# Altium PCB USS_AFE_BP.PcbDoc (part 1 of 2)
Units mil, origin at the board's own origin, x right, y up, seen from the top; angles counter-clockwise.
Board outline 2300 x 2500 mil, 4 copper layers (Top Layer, GND, PWR, Bottom Layer), stack 59 mil thick; 119 components, 70 nets, 303 pads, 68 vias.
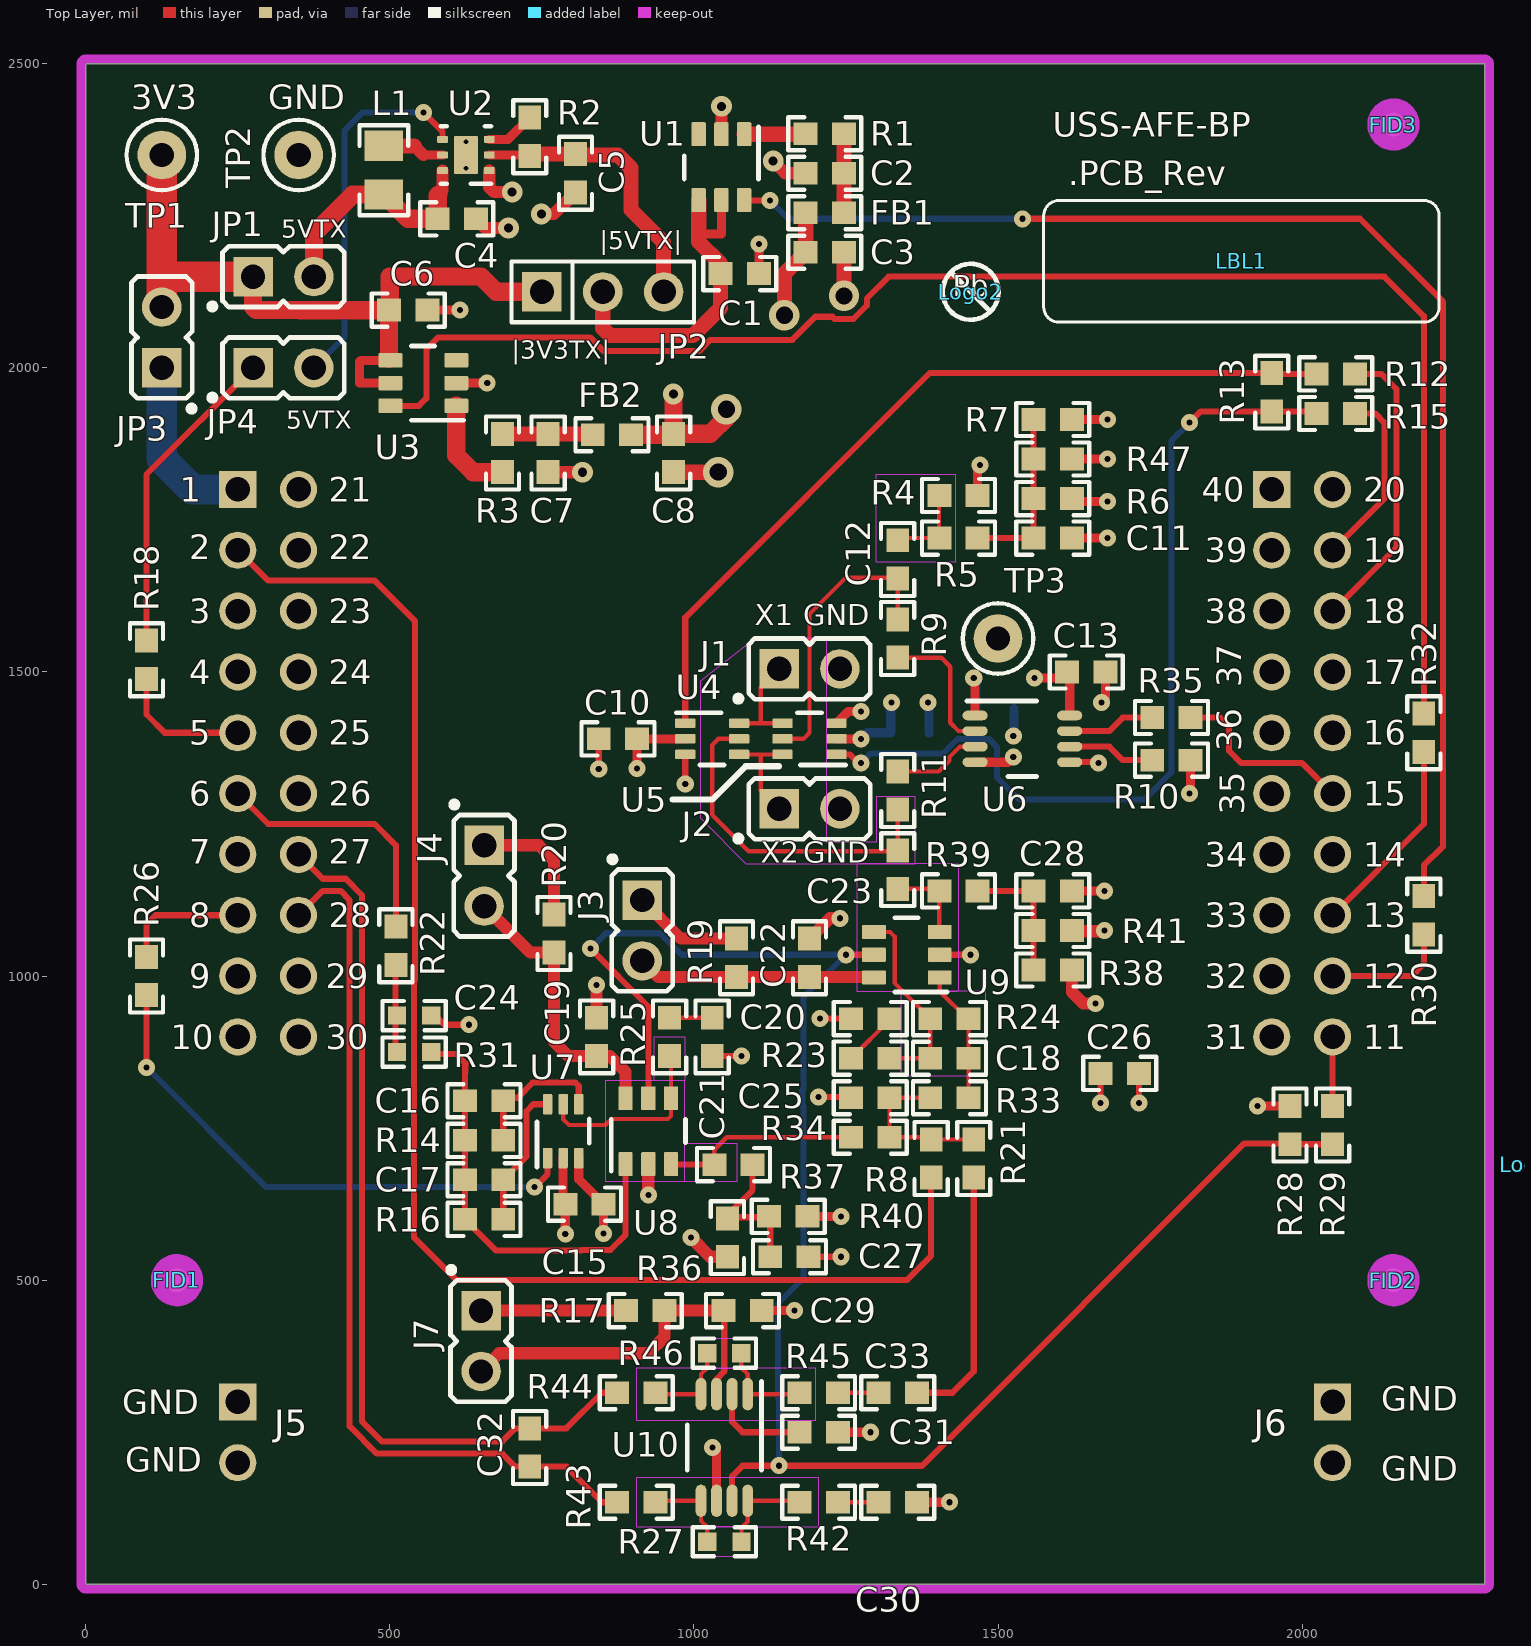
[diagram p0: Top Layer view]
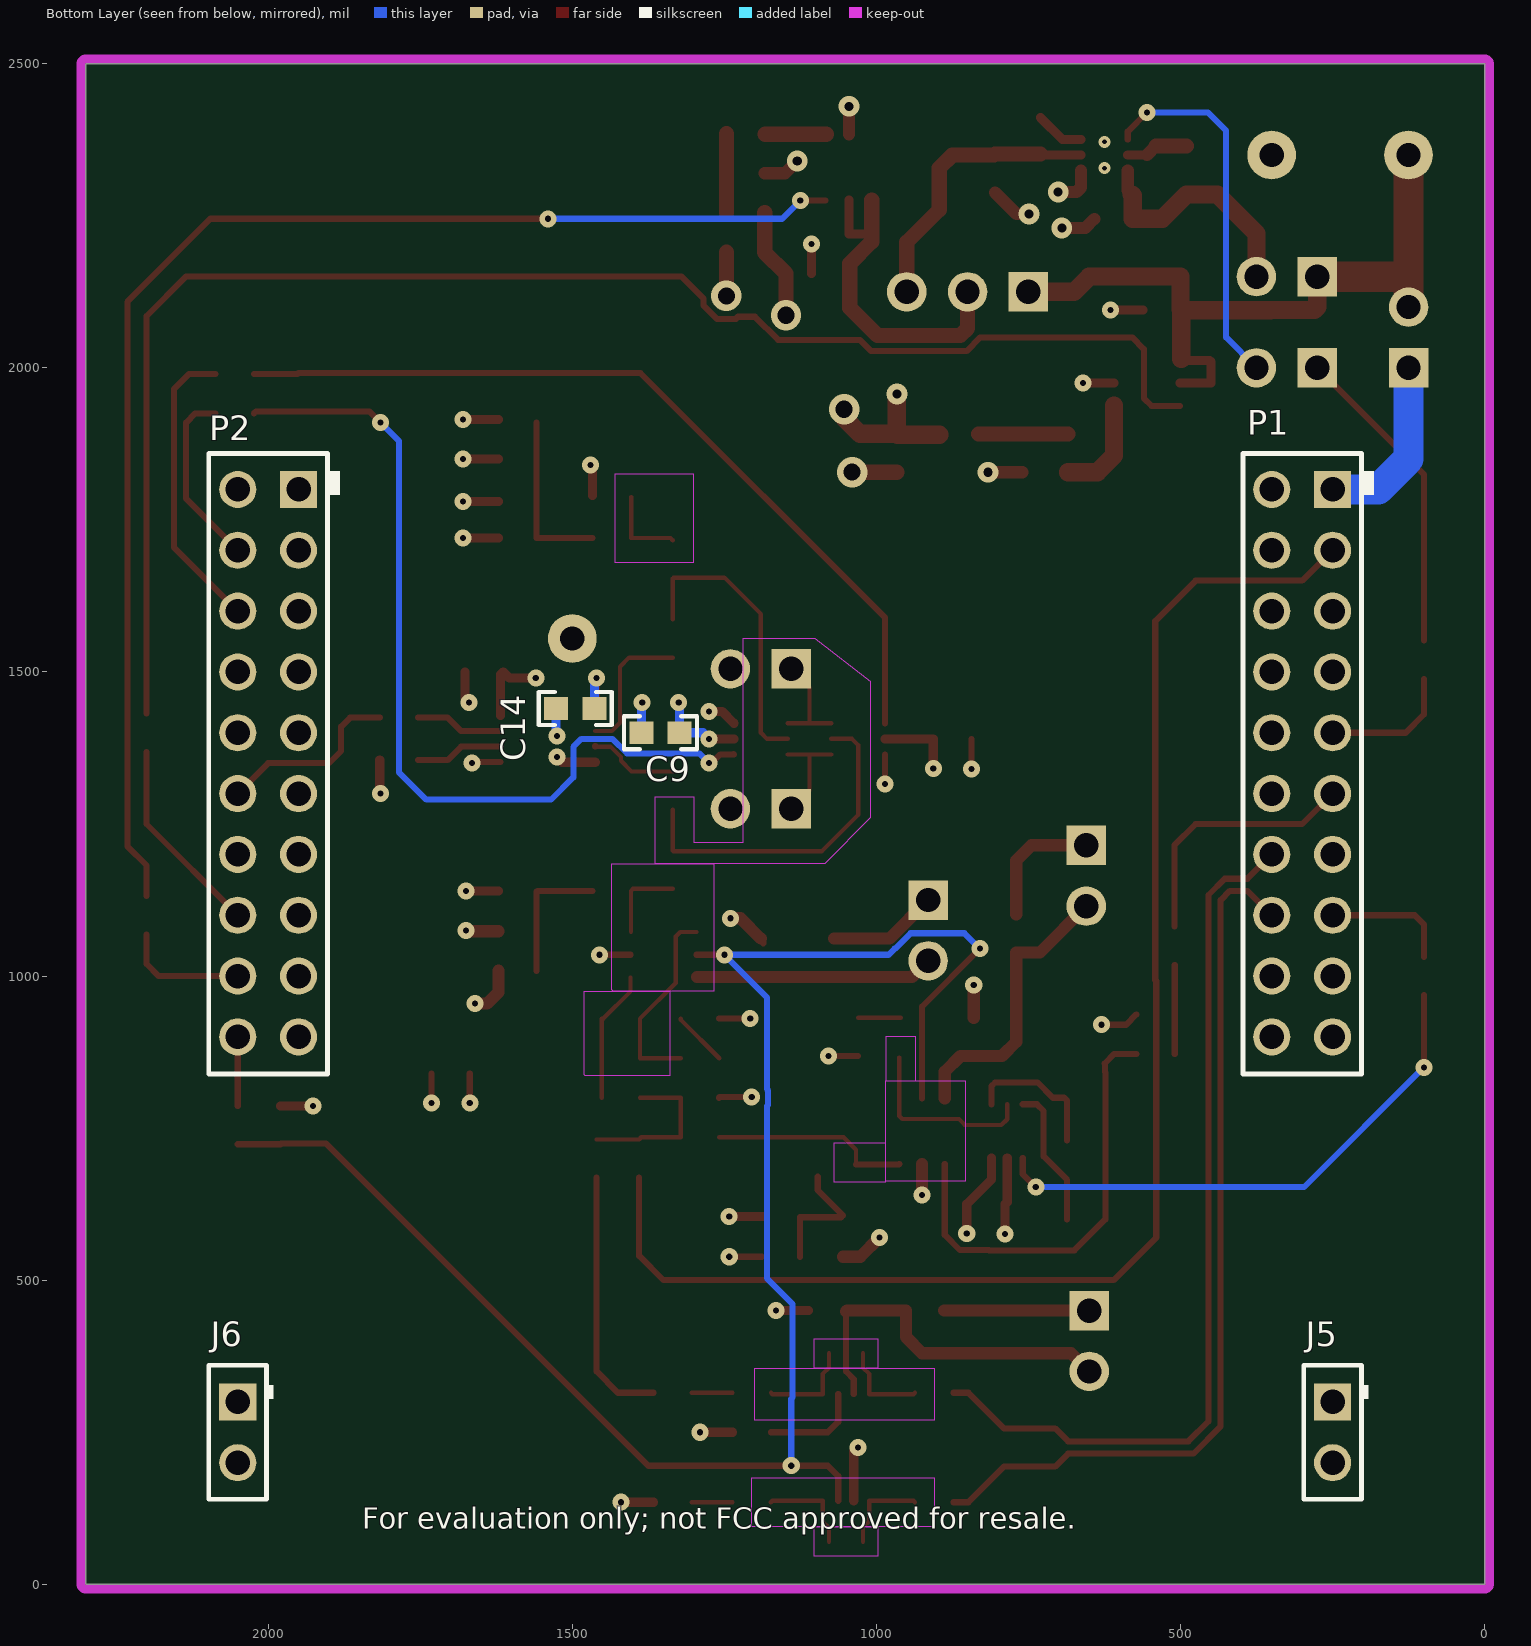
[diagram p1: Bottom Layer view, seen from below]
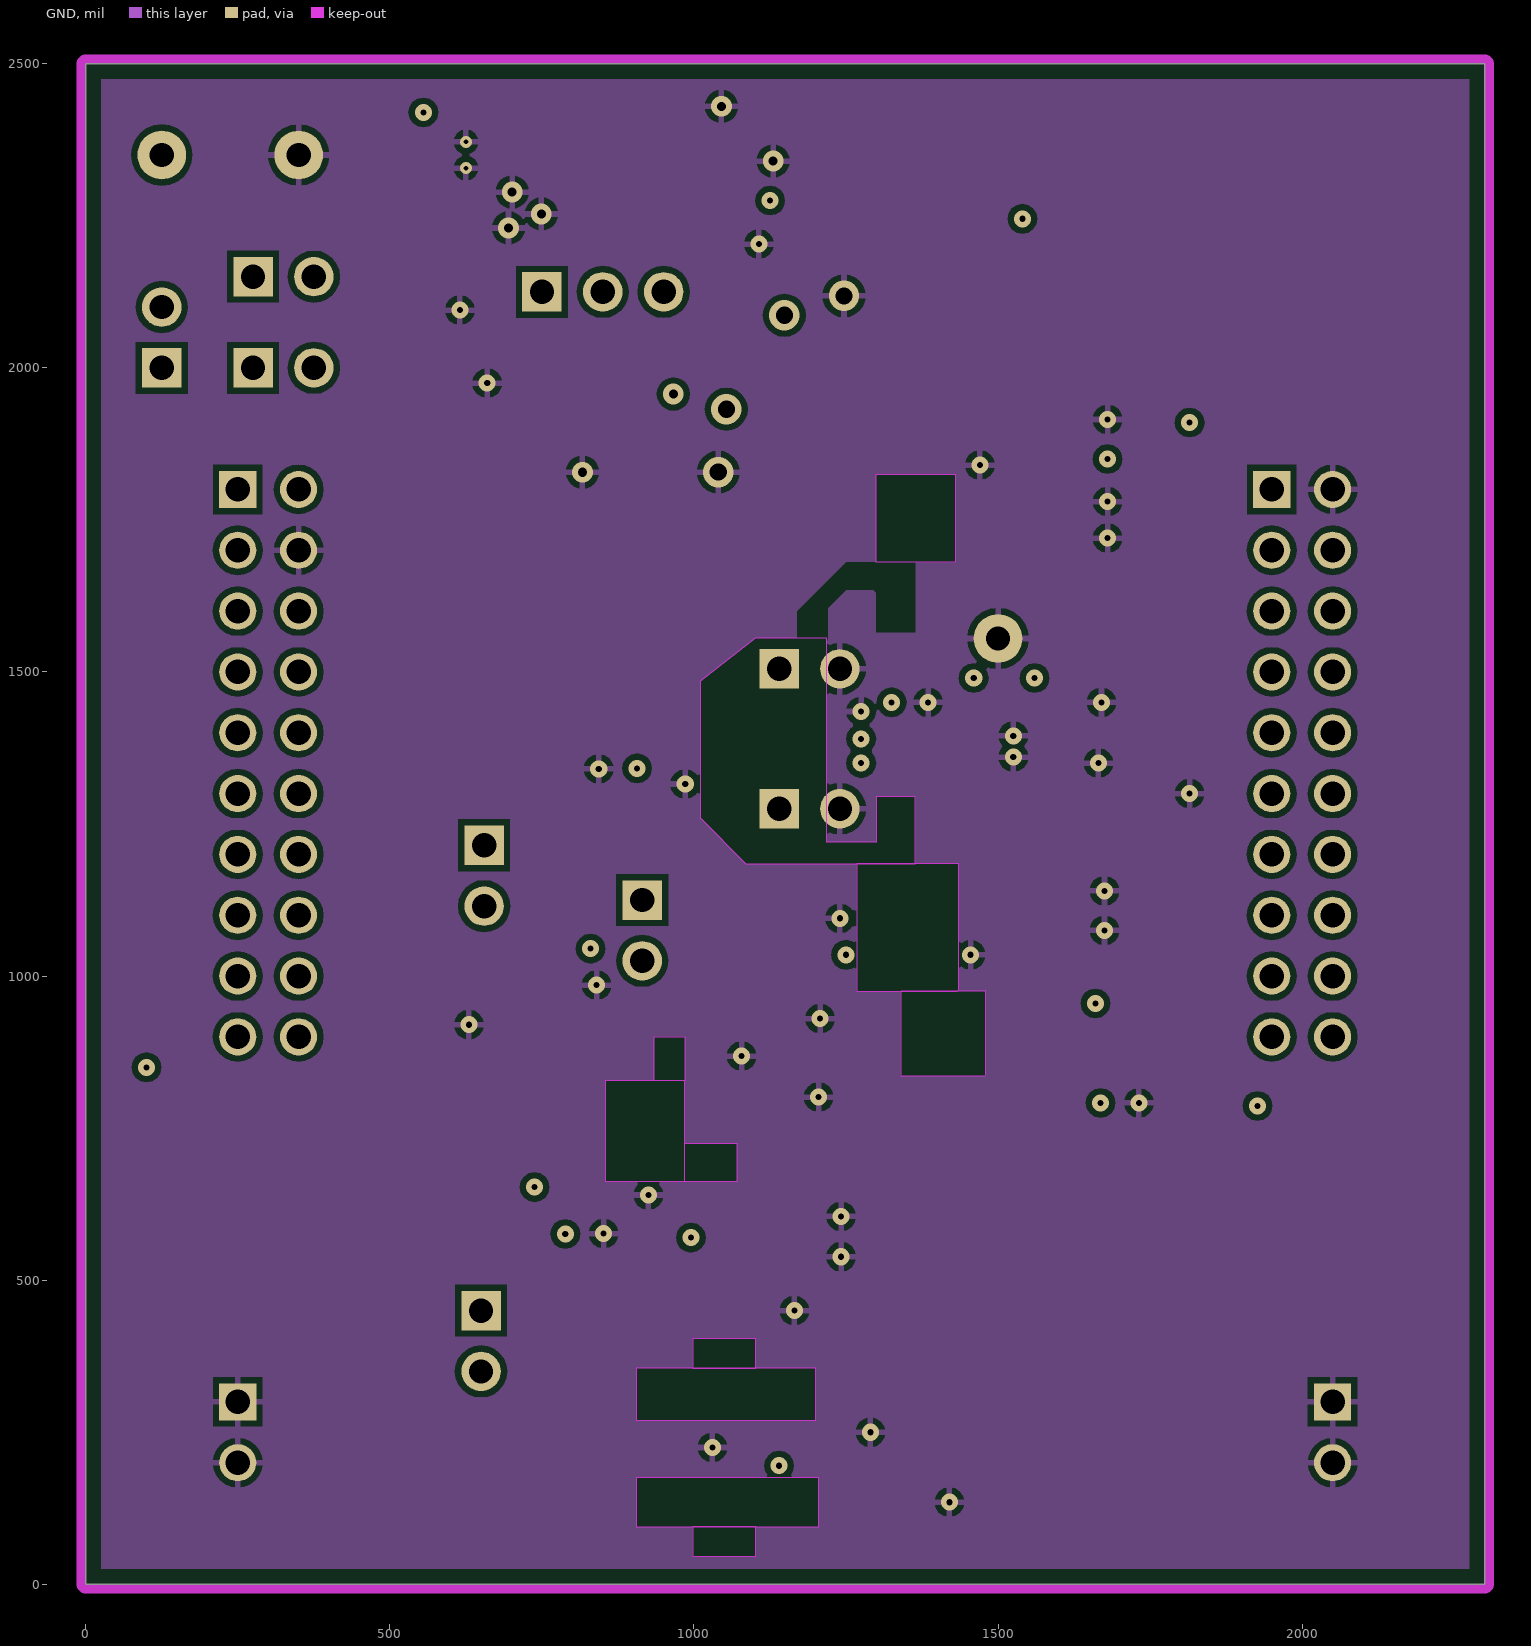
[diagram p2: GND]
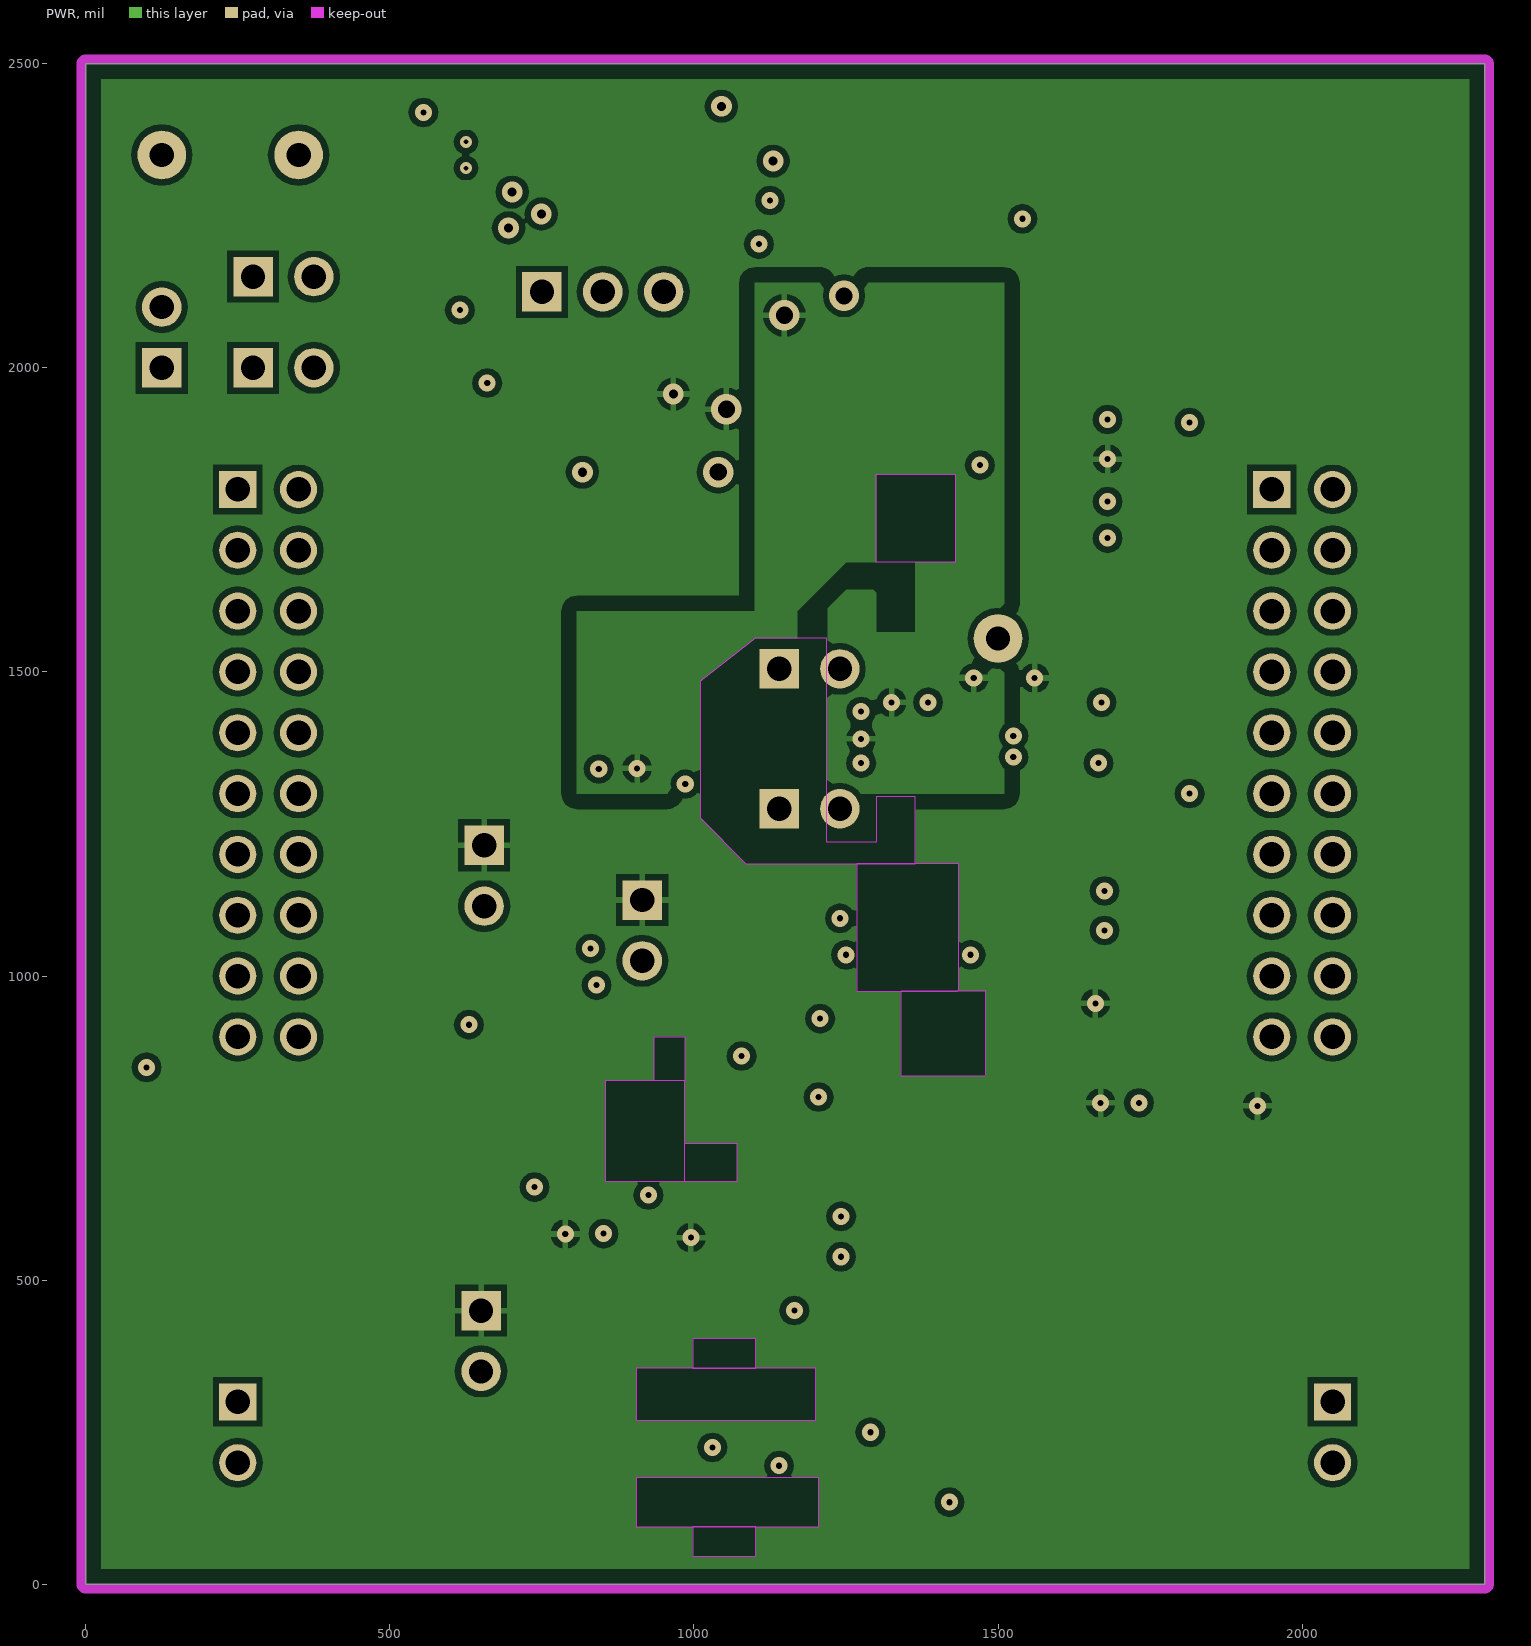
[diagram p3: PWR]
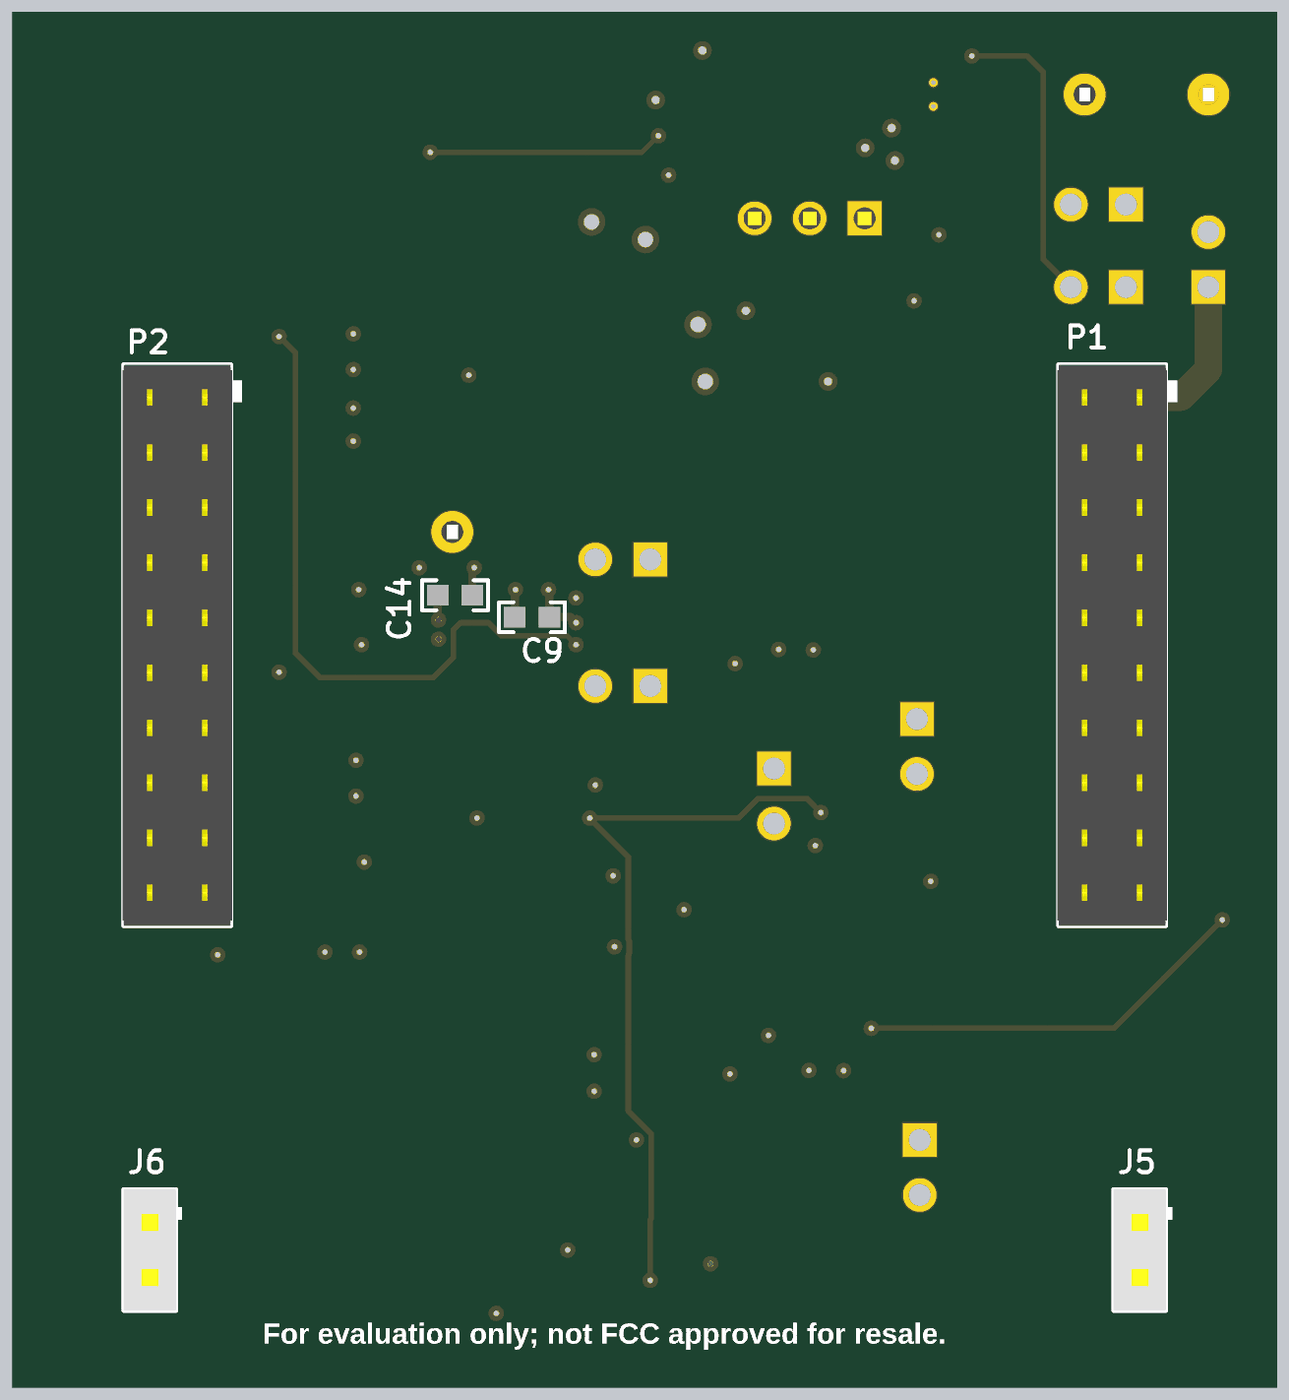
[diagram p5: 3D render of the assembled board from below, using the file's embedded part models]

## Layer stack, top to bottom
Top Solder: solder mask 0.4, Solder Resist, Dk 3.5
Top Layer: signal copper 0.7
Dielectric1: core 7.6, FR-4, Dk 4.3
GND: signal copper 1.2
Dielectric 3: prepreg 40, FR-4, Dk 4.3
PWR: signal copper 1.2
Dielectric 2: core 7.6, FR-4, Dk 4.3
Bottom Layer: signal copper 0.7
Bottom Solder: solder mask 0.4, Solder Resist, Dk 3.5

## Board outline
0,0 2300,0 2300,2500 0,2500

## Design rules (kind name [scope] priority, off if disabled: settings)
AcuteAngle [All] p1: minimum=4.50000000000000E+0001 checktracksonly=FALSE
AssemblyTestPointUsage [All] p1: valid=2
Clearance Clearance_Keepouts [((IsTrack Or IsArc) And Not InPoly) And IsFree and IsKeepOut vs ((IsTrack Or IsArc) And Not InPoly) And IsFree and IsKeepOut] p1: gap=0
Clearance Clearance_BoardEdge_MountingHoles [OnCopper and InComponentClass('Mounting Holes') vs IsKeepOut] p2: gap=40
Clearance Clearance_BoardEdge_Poly [OnCopper and InPoly vs IsKeepOut] p3: gap=25
Clearance Clearance_BoardEdge [OnCopper and Not InComponentClass('Logo') and not InComponentClass('FiducialMark') and not InRegion(1000,500,4000,800) and Not IsKeepout vs IsKeepOut] p4: gap=75 except(25: Track-SMDPad Track-THPad; 50: Arc-Via Track-Track Track-Via Via-Region)
Clearance Clearance_Poly [InPolygon] p5: gap=25 except(10: THPad-Poly Via-Poly)
Clearance [All] p6: gap=7.87
ComponentClearance ComponentClearance_MountingHoles_FiducialMarks [InComponentClass('Mounting Holes') vs InComponentClass('FiducialMark')] p1: gap=50 collisioncheckmode=3 verticalgap=10 showdistances=FALSE
ComponentClearance ComponentClearance_Shunt [InComponentClass('Header') vs InComponentClass('Shunt')] p2: gap=0 collisioncheckmode=3 verticalgap=0 showdistances=FALSE
ComponentClearance ComponentClearance_Logo [InComponentClass('Logo')] p3: gap=10 collisioncheckmode=3 verticalgap=10 showdistances=FALSE
ComponentClearance ComponentClearance_ScrewToNut [(HasFootprint('NY PMS 440 0025 PH')) vs (HasFootprint('Keystone_1902C'))] p4: gap=5 collisioncheckmode=3 verticalgap=10 showdistances=FALSE
ComponentClearance ComponentClearance_MountingHoles [InComponentClass('Mounting Holes')] p5: gap=250 collisioncheckmode=3 verticalgap=100000 showdistances=FALSE
ComponentClearance ComponentClearance_SmallPassives [HasFootprint('0201*') or HasFootprint('0402*') or HasFootprint('0508') or HasFootprint('0603*') or HasFootprint('0612') or HasFootprint('0805*') or HasFootprint('0815*') or HasFootprint('0830*') or HasFootprint('1206*') or HasFootprint('1210*') or HasFootprint('1808*') or HasFootprint('1812*') or HasFootprint('1825*') or HasFootprint('2010*') or HasFootprint('2220*') or HasFootprint('2225*') or HasFootprint('2512*') or HasFootprint('2728*') or HasFootprint('3518*') vs HasFootprint('0201*') or HasFootprint('0402*') or HasFootprint('0508') or HasFootprint('0603*') or HasFootprint('0612') or HasFootprint('0805*') or HasFootprint('0815*') or HasFootprint('0830*') or HasFootprint('1206*') or HasFootprint('1210*') or HasFootprint('1808*') or HasFootprint('1812*') or HasFootprint('1825*') or HasFootprint('2010*') or HasFootprint('2220*') or HasFootprint('2225*') or HasFootprint('2512*') or HasFootprint('2728*') or HasFootprint('3518*')] p6: gap=20 collisioncheckmode=3 verticalgap=10 showdistances=FALSE
ComponentClearance ComponentClearance_THtoSMT [IsThruComponent vs IsSMTComponent] p7: gap=20 collisioncheckmode=3 verticalgap=30 showdistances=FALSE
ComponentClearance ComponentClearance_THtoTH [IsThruComponent vs IsThruComponent] p8: gap=10 collisioncheckmode=3 verticalgap=30 showdistances=FALSE
ComponentClearance [All] p9: gap=20 collisioncheckmode=3 verticalgap=10 showdistances=FALSE
DiffPairsRouting [All] p1: maxlimit=100 minlimit=10 mostfreqgap=10 toplayer_minwidth=10 toplayer_maxwidth=10 toplayer_prefwidth=10 midlayer1_minwidth=10 midlayer1_maxwidth=10 midlayer1_prefwidth=10 midlayer2_minwidth=10 midlayer2_maxwidth=10 midlayer2_prefwidth=10 bottomlayer_minwidth=10 bottomlayer_maxwidth=10 bottomlayer_prefwidth=10 maxuncoupledlength=1000
FabricationTestPointUsage TestPointUsage [All] p1: valid=2 allowmultiple=FALSE
FabricationTestpoint Testpoint [All] p1: side=3 testpointundercomponent=TRUE minsize=40 maxsize=100 preferedsize=60 minholesize=0 maxholesize=40 preferedholesize=32 testpointgrid=1 allowsidetop=TRUE allowsidebottom=TRUE usegrid=TRUE gridtolerance=0.01
FanoutControl Fanout_LCC [IsLCC] p1: bgadir=Out bgaviamode=Centered fanoutstyle=Auto fanoutdirection=Alternating viagrid=1 // Fanout_LCC (Default Rule)
FanoutControl Fanout_BGA [IsBGA] p2: bgadir=Out bgaviamode=Centered fanoutstyle=Auto fanoutdirection=Alternating viagrid=1 // Fanout_BGA (Default Rule)
FanoutControl Fanout_Default [All] p4: bgadir=Out bgaviamode=Centered fanoutstyle=Auto fanoutdirection=Alternating viagrid=1 // Fanout_Default (Default Rule)
FanoutControl Fanout_Small [(CompPinCount < 5)] p5: bgadir=Out bgaviamode=Centered fanoutstyle=Auto fanoutdirection=OutThenIn viagrid=1 // Fanout_Small (Default Rule)
HoleSize [All] p1: absolutevalues=TRUE maxlimit=251 minlimit=7.85 maxpercent=80.000 minpercent=20.000
MinimumAnnularRing MinimumAnnularRing_ThermalPadVias [IsVia and InAnyComponent] p1: minimumring=5.91
MinimumAnnularRing [All] p2: minimumring=9
MinimumSolderMaskSliver MinimumSolderMaskSliver_Logo [InComponentClass('Logo') vs InComponentClass('Logo')] p1: minsoldermaskwidth=0.7
MinimumSolderMaskSliver [All] p2: minsoldermaskwidth=3.94
PlaneConnect [All] p1: planeconnectstyle=Relief reliefexpansion=10 reliefentries=4 reliefconductorwidth=10 reliefairgap=10
PolygonConnect [All] p1: connectstyle=Relief reliefconductorwidth=10 reliefentries=4 polygonreliefangle="90 Angle" airgapwidth=10
RoutingVias ThermalPadVias [IsVia and InAnyComponent] p1: holewidth=7.87 width=19.68 viastyle="Through Hole" minholewidth=7.87 minwidth=19.68 maxholewidth=12.99 maxwidth=23.62
RoutingVias [All] p2: holewidth=16 width=34 viastyle="Through Hole" minholewidth=7.87 minwidth=26 maxholewidth=40 maxwidth=65
SilkToBoardRegionClearance [Not ((IsComment or IsDesignator) And (Hide <> 'False')) and not InRegion(1000,500,4000,800)] p1:
SilkToSilkClearance SilkToSilkClearance_Pb-FreeLogo [(HasFootprint('Pb-Free_Overlay_Medium') OR HasFootprint('Pb-Free_Overlay_Small')) vs (HasFootprint('Pb-Free_Overlay_Medium') OR HasFootprint('Pb-Free_Overlay_Small'))] p1: silktosilkclearance=0
SilkToSilkClearance [All] p2: silktosilkclearance=5
SilkToSolderMaskClearance "Silk to Solder Mask Opening" [All] p1: minsilkscreentomaskgap=1 clearancetoexposedcopper=FALSE
SolderMaskExpansion [All] p1: expansion=-1.99
Width [All] p1: maxlimit=100 minlimit=6 preferedwidth=10 checkconnectedcopper=TRUE
15 further rules are at their usual default settings.

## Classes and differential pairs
component class USS_AFE_BP_AFE: C1 C2 C3 C4 C5 C6 C7 C8 C9 C10 C11 C12 C13 C14 C15 C16 C17 C18 C19 C20 C21 C22 C23 C24 C25 C26 C27 C28 C29 C30 C31 C32 C33 FB1 FB2 J1 J2 J3 J4 J5 J6 J7 JP1 JP2 JP3 JP4 L1 P1 P2 R1 R2 R3 R4 R5 R6 R7 R8 R9 R10 R11 R12 R13 R14 R15 R16 R17 R18 R19 R20 R21 R22 R23 R24 R25 R26 R27 R28 R29 R30 R31 R32 R33 R34 R35 R36 R37 R38 R39 R40 R41 R42 R43 R44 R45 R46 R47 TP1 TP2 TP3 U1 U2 U3 U4 U5 U6 U7 U8 U9 U10
component class Header: J1 J2 J3 J4 J7 JP1 JP2 JP3 JP4
component class AssemblyNote: ZZ1 ZZ2 ZZ3 ZZ4
component class FiducialMark: FID1 FID2 FID3
component class USS_AFE_BP_Hardware: FID1 FID2 FID3 LBL1 Logo2 ZZ1 ZZ2 ZZ3 ZZ4
component class Label: LBL1
differential pair ADC: +ADC_P -ADC_N

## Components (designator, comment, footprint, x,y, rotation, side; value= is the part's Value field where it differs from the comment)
C1 "CL10A226MP8NUNE" 0603 1075.18,2154.88 r0 top
C2 "GRM188R61C225KE15D" 0603 1215.18,2319.88 r180 top
C3 "GRM188R61C225KE15D" 0603 1215.18,2189.88 r0 top
C4 "GRM188R61C225KE15D" 0603 610.18,2244.89 r0 top
C5 "GRM188R61C475KAAJ" 0603 805.18,2319.88 r270 top
C6 "CL10A226MP8NUNE" 0603 530.18,2094.88 r0 top
C7 "GRM188R61C225KE15D" 0603 760.18,1859.88 r270 top
C8 "GRM188R61C225KE15D" 0603 966.47,1859.88 r270 top
C9 "GRM188R71E104KA01D" 0603 1355,1400 r0 bottom
C10 "GRM188R71E104KA01D" 0603 875,1390 r180 top
C11 "GRM188R61C225KE15D" 0603 1590,1720 r180 top
C12 "GRM188R71C105KA12D" 0603 1335,1685 r90 top
C13 "GRM188R71E104KA01D" 0603 1645,1500 r180 top
C14 "GRM188R71E104KA01D" 0603 1495,1440 r0 bottom
C15 "GRM188R71E104KA01D" 0603 820,625 r0 top
C16 "GRM1885C1H621JA01D" 0603 655,795 r0 top
C17 "GRM1885C1H680JA01D" 0603 655,665 r0 top
C18 "GRM1885C1H330JA01D" 0603 1420,865 r180 top
C19 "GRM188R71E104KA01D" 0603 840,900 r90 top
C20 "GRM188R71C105KA12D" 0603 1290,930 r0 top
C21 "GRM188R71C105KA12D" 0603 1030,900 r90 top
C22 "GRM188R71E104KA01D" 0603 1190,1030 r90 top
C23 "GRM188R71C105KA12D" 0603 1335,1175 r270 top
C24 "C0603C472J5RACTU" 0603_HV 540,935 r0 top
C25 "GRM1885C1H681JA01D" 0603 1290,800 r180 top
C26 "GRM188R61C225KE15D" 0603 1700,840 r180 top
C27 "GRM188R61C225KE15D" 0603 1156.95,538.54 r180 top
C28 "GRM188R61C225KE15D" 0603 1590,1140 r180 top
C29 "GRM188R71E104KA01D" 0603 1080,450 r0 top
C30 "GRM188R71C105KA12D" 0603 1335,135 r0 top
C31 "GRM188R71A224KA01D" 0603 1205,250 r0 top
C32 "GRM188R71H561KA01D" 0603 730,225 r90 top
C33 "GRM188R71C105KA12D" 0603 1335,315 r180 top
FB1 "MPZ1608S221A" 0603 1215.18,2254.88 r180 top
FB2 "MPZ1608S221A" 0603 865.18,1889.88 r0 top
FID1 "Fiducial" Fiducial10-20 150,500 r0 top
FID2 "Fiducial" Fiducial10-20 2150,500 r0 top
FID3 "Fiducial" Fiducial10-20 2150,2400 r0 top
J1 "PBC02SAAN" Sullins_PBC02SAAN 1190,1505 r90 top
J2 "PBC02SAAN" Sullins_PBC02SAAN 1190,1275 r90 top
J3 "PBC02SAAN" Sullins_PBC02SAAN 915,1075 r0 top
J4 "PBC02SAAN" Sullins_PBC02SAAN 655,1165 r0 top
J5 "SSQ-102-03-F-S" Samtec_SSQ-102-03-x-S 250,250 r270 bottom locked
J6 "SSQ-102-03-F-S" Samtec_SSQ-102-03-x-S 2050,250 r270 bottom locked
J7 "PBC02SAAN" Sullins_PBC02SAAN 650,400 r0 top
JP1 "PBC02SAAN" Sullins_PBC02SAAN 325.18,2149.88 r90 top
JP2 "PBC03SAAN" PBC03SAAN 850.18,2124.88 r0 top
JP3 "PBC02SAAN" Sullins_PBC02SAAN 125.18,2049.88 r180 top
JP4 "PBC02SAAN" Sullins_PBC02SAAN 325.18,1999.88 r90 top
L1 "LQM21PN1R0MC0D" 0805_HV 490.18,2324.88 r270 top
LBL1 "Size: 0.65\" x 0.20 \"" Label_650x200 1900,2175 r0 top
Logo2 "Pb-Free Symbol" Pb-Free_Overlay_Small 1455,2125 r0 top
Logo3 "FCC disclaimer" FCC_disclaimer 2378,691 r90 top
P1 "ESQ-110-13-T-D-LL" Samtec_ESQ-110-13-x-D-LL 300,1350 r270 bottom locked
P2 "ESQ-110-13-T-D-LL" Samtec_ESQ-110-13-x-D-LL 2000,1350 r270 bottom locked
R1 "RC0603JR-070RL" 0603 1215.18,2384.88 r180 top
R2 "RC0603JR-070RL" 0603 730.18,2379.88 r90 top
R3 "RC0603JR-070RL" 0603 685.18,1859.88 r270 top
R4 "RC0603FR-07200KL" 0603 1435,1790 r0 top
R5 "RC0603FR-0724K9L" 0603 1435,1720 r180 top
R6 "RC0603FR-072ML" 0603 1590,1785 r180 top
R7 "RC0603FR-072ML" 0603 1590,1915 r180 top
R8 "RC0603JR-070RL" 0603 1390,700 r90 top
R9 "RC0603FR-07806RL" 0603 1335,1555 r90 top
R10 "RC0603JR-070RL" 0603 1785,1355 r0 top
R11 "RC0603FR-07806RL" 0603 1335,1305 r270 top
R12 "RC0603JR-070RL" 0603 2055,1990 r180 top
R13 "RC0603JR-070RL" 0603 1950,1960 r270 top
R14 "RC0603FR-07402RL" 0603 655,730 r180 top
R15 "RC0603JR-070RL" 0603 2055,1925 r180 top
R16 "RC0603FR-072KL" 0603 655,600 r180 top
R17 "RC0603JR-070RL" 0603 920,450 r180 top
R18 "RC0603JR-070RL" 0603 100,1520 r270 top
R19 "RC0603JR-070RL" 0603 1070,1030 r90 top
R20 "RC0603JR-070RL" 0603 770,1070 r90 top
R21 "RC0603JR-070RL" 0603 1460,700 r90 top
R22 "RC0603JR-070RL" 0603 510,1050 r90 top
R23 "RC0603FR-0710RL" 0603 1290,865 r0 top
R24 "RC0603FR-071K82L" 0603 1420,930 r0 top
R25 "RC0603FR-0749R9L" 0603 960,900 r270 top
R26 "RC0603JR-070RL" 0603 100,1000 r90 top
R27 "RC0603FR-07402RL" 0603_HV 1050,70 r180 top
R28 "RCG060310K0FKEA" 0603 1980,755 r270 top
R29 "RC0603JR-070RL" 0603 2050,755 r90 top
R30 "RC0603JR-070RL" 0603 2200,1100 r270 top
R31 "RC0603FR-0775RL" 0603_HV 540,875 r180 top
R32 "RC0603JR-070RL" 0603 2200,1400 r270 top
R33 "RC0603FR-07499RL" 0603 1420,800 r180 top
R34 "RC0603JR-070RL" 0603 1290,735 r0 top
R35 "RC0603JR-070RL" 0603 1785,1425 r0 top
R36 "RC0603FR-072ML" 0603 1055,570 r270 top
R37 "RC0603FR-0724K9L" 0603 1065,690 r180 top
R38 "RC0603FR-072ML" 0603 1590,1010 r0 top
R39 "RC0603FR-0724K9L" 0603 1435,1140 r180 top
R40 "RC0603FR-072ML" 0603 1155,605 r180 top
R41 "RC0603FR-072ML" 0603 1590,1075 r180 top
R42 "RC0603FR-0749R9L" 0603 1205,135 r180 top
R43 "RC0603FR-0749R9L" 0603 905,135 r180 top
R44 "RC0603FR-0749R9L" 0603 905,315 r180 top
R45 "RC0603FR-0749R9L" 0603 1205,315 r180 top
R46 "RC0603FR-07402RL" 0603_HV 1049.87,380 r180 top
R47 "RC0603FR-072ML" 0603 1590,1850 r0 top
TP1 "5003" Keystone5003 125.18,2349.88 r0 top
TP2 "5001" Keystone5001#1 350.18,2349.88 r0 top
TP3 "5001" Keystone5001#2 1755,1560 r0 top
U1 "TPS22860DBVR" DBV0006A_N 1045.18,2329.88 r270 top
U2 "TPS61240DRVR" DRV0006A 625.18,2349.88 r180 top
U3 "TPS22860DBVR" DBV0006A_N 555.18,1974.88 r180 top
U4 "TS5A9411DCKR" DCK0006A_N 1030,1390 r0 top
U5 "TS5A9411DCKR" DCK0006A_N 1190,1390 r180 top
U6 "SN74LVC2T45DCTR" DCT0008A_N 1540,1390 r0 top
U7 "TS5A9411DCKR" DCK0006A_N 785,745 r90 top
U8 "OPA835IDBVT" DBV0006A_N 925,745 r90 top
U9 "OPA836IDBVT" DBV0006A_N 1350,1035 r180 top
U10 "THS4531IDGK" DGK0008A_N 1050,225 r270 top
ZZ1 "This Assembly Note is for PCB labels only" AssemblyNoteLabel 185,3938 r0 top
ZZ2 "These assemblies are ESD sensitive, ESD precautions shall be observed." AssemblyNote 185,3829.11 r0 top
ZZ3 "These assemblies must be clean and free from flux and all contaminants. Use of no clean flux is not acceptable." AssemblyNote 185,3740.56 r0 top
ZZ4 "These assemblies must comply with workmanship standards IPC-A-610 Class 2, unless otherwise specified." AssemblyNote 185,3652 r0 top

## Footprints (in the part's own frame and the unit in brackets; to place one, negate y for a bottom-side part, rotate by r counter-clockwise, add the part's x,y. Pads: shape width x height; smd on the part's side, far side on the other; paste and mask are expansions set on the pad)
0603 [mm] "0603 from SM-752 data"
  rect 1x0.95 smd: 1(-0.8,0) 2(0.8,0)
  silkscreen extent -1.52,-0.69 1.52,0.69, body extent -0.87,-0.47 0.87,0.47, height 1
0603_HV [mil] "Ernesto recommended land pattern.  26 mil between pads."
  rect 30x30 smd: 1(-28,0) 2(28,0)
  silkscreen extent -52,-24 52,24, body extent -34,-19 34,19, height 39
0805_HV [mil] "0805 with 30mil clearance between pads"
  rect 50x63 smd: 1(-40,0) 2(40,0)
  silkscreen extent -74,-40 74,40, body extent -43,-29 43,29, height 57
AssemblyNote [mil] "Assembly Note"
AssemblyNoteLabel [mil] "Assembly Note for PCB Labels"
DBV0006A_N [mm] "SOT23, 6-Leads, Body 2.9x1.6mm, Pitch 0.95mm, Lead Span 2.8mm, IPC Medium Density"
  rrect17% 1x0.6 smd: 1(-1.375,0.95) 2(-1.375,0) 3(-1.375,-0.95) 4(1.375,-0.95) 5(1.375,0) 6(1.375,0.95)
  silkscreen extent -1.68,-1.55 0.5,1.55, body extent -1.42,-1.46 1.42,1.46, height 1.12
DCK0006A_N [mm] "SOT23, 6-Leads, Body 2x1.3mm, Pitch 0.65mm, Lead Span 2.1mm, IPC Medium Density"
  rrect25% 0.85x0.4 smd: 1(-1.125,0.65) 2(-1.125,0) 3(-1.125,-0.65) 4(1.125,-0.65) 5(1.125,0) 6(1.125,0.65)
  silkscreen extent -1.5,-1.09 0.51,1.09, body extent -1.14,-1 1.14,1, height 0.95
DCT0008A_N [mm] "TSOP, 8-Leads, Body 3x2.8mm, Pitch 0.65mm, IPC Medium Density"
  oval 1.05x0.4 smd: 1(-1.975,0.975) 2(-1.975,0.325) 3(-1.975,-0.325) 4(-1.975,-0.975) 5(1.975,-0.975) 6(1.975,-0.325) 7(1.975,0.325) 8(1.975,0.975)
  silkscreen extent -2.32,-1.57 0.6,1.58, body extent -2.01,-1.47 2.01,1.48, height 1.3
DGK0008A_N [mm] "TSOP, 8-Leads, Body 3x3mm, Pitch 0.65mm, IPC Medium Density"
  oval 1.35x0.45 smd: 1(-2.225,0.975) 2(-2.225,0.325) 3(-2.225,-0.325) 4(-2.225,-0.975) 5(2.225,-0.975) 6(2.225,-0.325) 7(2.225,0.325) 8(2.225,0.975)
  silkscreen extent -2.75,-1.55 0.95,1.55, body extent -2.45,-1.5 2.45,1.5, height 0.96
DRV0006A [mm] "SON, 6-Leads, Body 2x2mm, Pitch 0.65mm, Thermal Pad 1.6x1mm, TI Recommended"
  rrect33% 0.45x0.3 smd: 1(-0.975,0.65) 2(-0.975,0) 3(-0.975,-0.65) 4(0.975,-0.65) 5(0.975,0) 6(0.975,0.65)
  rrect14% 1x0.7 on Top Paste: 7(0,0.45) 7(0,-0.45)
  rrect10% 1x1.6 smd paste-0.5: 7(0,0)
  silkscreen extent -1.05,-1.2 1.05,1.2, body extent -1.05,-1.05 1.05,1.05, height 0.81
FCC_disclaimer [mil]
Fiducial10-20 [mm]
  round 1 smd mask+0.5: 1(0,0)
  Top Layer keep-out circle w1.178: c0,0 r0.5
Keystone5001#1 [mil] "For Keystone 500x miniature loop terminals"
  round 80 hole 40: 1(0,0)
  silkscreen extent -58,-58 58,58, body extent -49,-49 49,49, height 182
Keystone5001#2 [mil] "For Keystone 500x miniature loop terminals"
  round 80 hole 40: 1(-255,-5)
  silkscreen extent -313,-63 -197,53, body extent -304,-54 -206,44, height 182
Keystone5003 [mil] "For Keystone 500x miniature loop terminals"
  round 80 hole 40: 1(0,0)
  silkscreen extent -58,-58 58,58, body extent -49,-49 49,49, height 182
Label_650x200 [mil] "Thermal Transfer Label"
  round 1 on Mech13: 0(0,0)
  silkscreen extent -325,-100 325,100, body extent -325,-100 325,100, height 1
Pb-Free_Overlay_Small [mil]
  silkscreen extent -46,-46 46,46
PBC03SAAN [mm] "Sullins 100mil, 1x3, 230 mil above insulator"
  rect 1.65x1.65 hole 1.016: 1(-2.54,0)
  round 1.65 hole 1.016: 2(0,0) 3(2.54,0)
  silkscreen extent -3.81,-1.27 3.81,1.27, body extent -3.81,-1.27 3.81,1.27, height 8.38
Samtec_ESQ-110-13-x-D-LL [mm] "Receptacle, 2.54mm, 10x2, TH"
  rect 1.55x1.55 hole 1.02: 1(-11.43,1.27)
  round 1.55 hole 1.02: 2(-11.43,-1.27) 3(-8.89,1.27) 4(-8.89,-1.27) 5(-6.35,1.27) 6(-6.35,-1.27) 7(-3.81,1.27) 8(-3.81,-1.27) 9(-1.27,1.27) 10(-1.27,-1.27) 11(1.27,1.27) 12(1.27,-1.27) 13(3.81,1.27) 14(3.81,-1.27) 15(6.35,1.27) 16(6.35,-1.27) 17(8.89,1.27) 18(8.89,-1.27) 19(11.43,1.27) 20(11.43,-1.27)
  silkscreen extent -12.93,-2.48 12.97,3, body extent -12.93,-2.54 12.98,2.54, height 11.06
Samtec_SSQ-102-03-x-S [mm] "Receptacle, 2.54mm, 2x1, TH"
  rect 1.55x1.55 hole 1.02: 1(-1.27,0)
  round 1.55 hole 1.02: 2(1.27,0)
  silkscreen extent -2.79,-1.21 2.79,1.5, body extent -2.79,-1.21 2.79,1.21, height 8.51
Sullins_PBC02SAAN [mm] "Sullins 100mil, 1x2, 230 mil above insulator"
  rect 1.65x1.65 hole 1.016: 1(0,1.27)
  round 1.65 hole 1.016: 2(0,-1.27)
  silkscreen extent -1.37,-2.54 1.27,3.1, body extent -1.27,-2.54 1.27,2.54, height 8.38

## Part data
C1 C6: "CAP, CERM, 22 µF, 10 V, +/- 20%, X5R, 0603"
C2 C3 C4 C7 C8 C11 C26 C27 C28: "CAP, CERM, 2.2 µF, 16 V, +/- 10%, X5R, 0603"
C5: "CAP, CERM, 4.7 µF, 16 V, +/- 10%, X5R, 0603"
C9 C10 C13 C14 C15 C19 C22 C29: "CAP, CERM, 0.1 µF, 25 V, +/- 10%, X7R, 0603"
C12 C20 C21 C23 C30 C33: "CAP, CERM, 1 µF, 16 V, +/- 10%, X7R, 0603"
C16: "CAP, CERM, 620 pF, 50 V, +/- 5%, C0G/NP0, 0603"
C17: "CAP, CERM, 68 pF, 50 V, +/- 5%, C0G/NP0, 0603"
C18: "CAP, CERM, 33 pF, 50 V, +/- 5%, C0G/NP0, 0603"
C24: "CAP, CERM, 4700 pF, 50 V, +/- 5%, X7R, 0603"
C25: "CAP, CERM, 680 pF, 50 V, +/- 5%, C0G/NP0, 0603"
C31: "CAP, CERM, 0.22 µF, 10 V, +/- 10%, X7R, 0603"
C32: "CAP, CERM, 560 pF, 50 V, +/- 10%, X7R, 0603"
FB1 FB2: "Ferrite Bead, 220 ohm @ 100 MHz, 2.2 A, 0603"
FID1 FID2 FID3: "Fiducial mark.  There is nothing to buy or mount."
J1 J2 J3 J4 J7 JP1 JP3 JP4: "Header, 100mil, 2x1, Gold, TH"
J5 J6: "Receptacle, 2.54mm, 2x1, Gold, TH"
JP2: "Header, 100mil, 3x1, Gold, TH"
L1: "Inductor, Multilayer, Ferrite, 1 µH, 0.8 A, 0.19 ohm, SMD"
LBL1: library part THT-14-423-10, "Thermal Transfer Printable Labels, 0.650\" W x 0.200\" H - 10,000 per roll"
Logo2: library part Pb-Free
Logo3: library part FCC_disclaimer, "FCC_disclaimer"
P1 P2: "Receptacle, 2.54mm, 10x2, Tin, TH"
R1 R2 R3 R8 R10 R12 R13 R15 R17 R18 R19 R20 R21 R22 R26 R29 R30 R32 R34 R35: "RES, 0, 5%, 0.1 W, 0603"
R4: "RES, 200 k, 1%, 0.1 W, 0603"
R5 R37 R39: "RES, 24.9 k, 1%, 0.1 W, 0603"
R6 R7 R36 R38 R40 R41 R47: "RES, 2.00 M, 1%, 0.1 W, 0603"
R9 R11: "RES, 806, 1%, 0.1 W, 0603"
R14 R27 R46: "RES, 402, 1%, 0.1 W, 0603"
R16: "RES, 2.00 k, 1%, 0.1 W, 0603"
R23: "RES, 10.0, 1%, 0.1 W, 0603"
R24: "RES, 1.82 k, 1%, 0.1 W, 0603"
R25 R42 R43 R44 R45: "RES, 49.9, 1%, 0.1 W, 0603"
R28: "RES, 10.0 k, 1%, 0.1 W, 0603"
R31: "RES, 75.0, 1%, 0.1 W, 0603"
R33: "RES, 499, 1%, 0.1 W, 0603"
TP1: "Test Point, Miniature, Orange, TH"
TP2 TP3: "Test Point, Miniature, Black, TH"
U1 U3: "Ultra-Low Leakage Load Switch, DBV0006A"
U2: "3.5-MHz High Efficiency Step-Up Converter,  DRV0006A"
U4 U5 U7: "10-O SPDT ANALOG SWITCH SINGLE-CHANNEL 2:1 MULTIPLEXER/DEMULTIPLEXER, DCK0006A"
U6: "Dual-Bit Dual-Supply Bus Transceiver With Configurable Voltage Translation and 3-State Outputs, DCT0008A"
U8: "Ultra Low Power, Rail-to-Rail Out, Negative Rail In, VFB Amplifier, 2.5 to 5.5 V, -40 to 125 degC, 6-pin SOT23 (DBV6), Green (RoHS & no Sb/Br)"
U9: "Very Low Power, Rail to Rail Out, Negative Rail In, VFB Operational Amplifier, 2.5 to 5.5 V, -40 to 125 degC, 6-pin SOT23 (DBV6), Green (RoHS & no Sb/Br)"
U10: "Ultra Low Power, Rail-to-Rail Output, Fully-Differential Amplifier, DGK0008A"
ZZ1: library part AssemblyNoteLabel
ZZ2 ZZ3 ZZ4: library part AssemblyNote

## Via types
v1: diameter 28, hole 10, Top Layer to Bottom Layer, tented both sides, 55 vias
v2: diameter 34, hole 15, Top Layer to Bottom Layer, tented both sides, 7 vias
v3: diameter 50, hole 28, Top Layer to Bottom Layer, tented both sides, 4 vias
v4: diameter 19.68, hole 7.87, Top Layer to Bottom Layer, 2 vias

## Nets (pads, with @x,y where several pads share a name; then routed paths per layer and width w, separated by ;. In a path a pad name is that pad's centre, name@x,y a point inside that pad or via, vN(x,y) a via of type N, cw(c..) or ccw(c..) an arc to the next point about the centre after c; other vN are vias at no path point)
ADC_N: C32.1 P1.16 R43.2 | length 1463.2
  Top Layer w10: P1.16@350,1100 390,1140 419,1140 434,1125 434,259.72 478.72,215 684.8,215 706.3,193.5 C32.1@730,193.5 790.32,193.5 848.82,135 R43.2@873.5,135
ADC_P: C32.2 P1.14 R44.2 | length 1463.2
  Top Layer w10: P1.14@350,1200 390,1160 427.28,1160 454,1133.28 454,268 487,235 684.8,235 706.3,256.5 C32.2@730,256.5 790.32,256.5 848.82,315 R44.2@873.5,315
AMP_PD-: R28.2 R29.1 U8.5 U9.5 U10.7 | length 2919.8
  Top Layer w10: v1(830,1045) 925,950 U8.5@925,799.13 ; U10.7@1062.79,137.4 1062.79,177.79 1080,195 v1(1140,195) 1375,195 1905,725 1978.5,725 R28.2@1980,723.5 R29.1@2050,723.5 ; v1(1250,1035) U9.5@1295.87,1035
  Bottom Layer w10: v1(830,1045) 855.35,1070.35 943.79,1070.35 969.14,1045 970,1045 980,1035 v1(1250,1035) 1180,965 1180,814.01 1178.13,812.13 1178.13,787.99 1180,786.12 1180,503.01 1138.13,461.13 1138.13,306.87 1140,305 v1(1140,195)
BP3V3: C6.1 JP1.1 JP2.1 JP3.2 TP1.1 U3.4 U3.5 | length 1205.1
  Top Layer w15: U3.5@501.04,1974.88 450.18,1974.88 450.18,2009.88 452.58,2012.29 U3.4@501.04,2012.29
  Top Layer w30: JP1.1@275.18,2149.88 275.18,2099.88 280.18,2094.88 351.89,2094.88 352.25,2094.53 C6.1@498.68,2094.53 ; U3.4@498.68,2014.65 C6.1@498.68,2094.53 ; C6.1@498.68,2094.88 C6.1@498.68,2094.53 ; C6.1@500,2096.21 500,2150 650,2150 675.12,2124.88 JP2.1@750.18,2124.88
  Top Layer w50: JP3.2@125.18,2099.88 TP1.1@125.18,2349.88 ; 128.18,2149.88 JP1.1@275.18,2149.88
DCDC_ENA: JP4.1 R18.1 | length 520.9
  Top Layer w10: R18.1@100,1551.5 100,1824.71 JP4.1@275.18,1999.88
GND: C1.2 C2.2 C3.2 C4.2 C5.2 C6.2 C7.2 C8.2 C9.2 C10.2 C11.1 C13.1 C14.2 C15.2 C19.2 C20.1 C21.1 C22.2 C24.2 C25.2 C26.1 C27.1 C28.1 C29.2 C30.2 C31.2 J1.2 J2.2 J5.1 J5.2 J6.1 J6.2 P1.4 P2.2 R4.2 R6.1 R7.1 R10.2 R40.1 R41.1 TP2.1 TP3.1 U1.2 U2.1 U2.7@625.18,2349.88 U3.2 U4.3 U5.3 U6.4 U6.5 U7.3 U8.2 U9.2 U10.6 | length 2453.8
  Top Layer w10: C24.2@572.5,937 589.5,920 v1(630,920) ; v1(843.5,1340.5) C10.2@843.5,1390 ; v1(985.71,1315.71) U4.3@985.71,1364.41 ; C21.1@1030,868.5 v1(1078.5,868.5) ; C22.2@1186,1053.99 C22.2@1186,1054.98 ; C27.1@1188.44,538.54 v1(1241.95,538.54) ; v1(1205,801) 1257.5,801 C25.2@1258.5,800 ; v1(1207.48,930) C20.1@1258.5,930 ; U9.2@1404.13,1035 v1(1455,1035) ; U6.5@1617.76,1351.61 1663.39,1351.61 v1(1665,1350) ; v1@1673.68,1073.68 v1(1675,1075) ; v1(1731.5,791.5) C26.1@1731.5,840
  Top Layer w15: C6.2@561.67,2094.88 v1(615.12,2094.88) ; U3.2@609.31,1974.88 v1(660.18,1974.88) ; U7.3@810.59,700.71 810.59,665.91 C15.2@851.5,625 v1(851.5,576.5) ; v1(1030.31,225) 1037.2,218.11 U10.6@1037.2,137.4 ; C1.2@1106.67,2154.88 v1(1106.67,2203.33) ; C29.2@1111.5,450 v1(1165,450) ; R40.1@1186.5,605 v1(1242,605) ; U5.3@1234.29,1415.59 1253.7,1435 v1(1275,1435) ; C31.2@1236.5,250 v1(1290,250) ; C30.2@1366.5,135 v1(1420,135) ; U6.4@1462.24,1351.61 1516.61,1351.61 v1(1525,1360) ; R4.2@1466.5,1790 1466.5,1836.5 v1(1470,1840) ; C28.1@1621.5,1140 v1(1675,1140) ; C11.1@1621.5,1720 v1(1680,1720) ; R6.1@1621.5,1780 v1(1680,1780) ; R7.1@1621.5,1915 v1(1680,1915) ; v1(1670,1450) 1676.5,1456.5 C13.1@1676.5,1500 ; v1(1815,1300) 1816.5,1301.5 R10.2@1816.5,1355
  Top Layer w20: C4.2@641.67,2244.89 656.67,2229.89 v2(695.18,2229.89) ; U2.1@663.56,2324.29 663.56,2296.5 671.18,2288.88 v2(701.18,2288.88) ; v2(749.18,2252.88) 769.67,2252.88 C5.2@805.18,2288.39 ; C7.2@760.18,1828.39 v2(816.67,1828.39) ; C19.2@840,931.5 v1(840,985) ; v1(925,640) U8.2@925,690.87 ; U1.2@1045.18,2384.02 v2(1045.18,2429.88) v2@1045.18,2434.88 ; v2(1130.18,2339.88) 1150.18,2319.88 C2.2@1183.68,2319.88 ; C22.2@1190,1061.5 1223.5,1095 v1(1240,1095) ; R41.1@1621.5,1073.68 v1@1673.68,1073.68
  Top Layer w25: C8.2@966.47,1828.39 v3(1039.98,1828.39) ; v3(1246.67,2118.39) C3.2@1246.67,2189.88
  Bottom Layer w15: v1(1385,1450) 1386.5,1448.5 C9.2@1386.5,1400 ; v1(1525,1395) 1526.5,1396.5 C14.2@1526.5,1440
  other v4: 625.18,2328.23 625.18,2371.54
LP3V3: JP3.1 P1.1 | length 295.4
  Bottom Layer w50: JP3.1@125.18,1999.88 125.18,1850.12 175.29,1800 P1.1@250,1800
LP5V: P1.2
MOSI: R35.1 U6.7 | length 144.9
  Top Layer w10: U6.7@1617.76,1402.8 1682.8,1402.8 1705,1425 R35.1@1753.5,1425
NetC1_1: C1.1 JP2.2 U1.4 U1.5 | length 562.8
  Top Layer w15: 1007.77,2219.88 1045.18,2219.88 U1.5@1045.18,2275.75
  Top Layer w25: JP2.2@850.18,2124.88 850.18,2064.88 862.18,2052.88 998.18,2052.88 1043.68,2098.39 C1.1@1043.68,2154.88 1043.68,2171.38 1007.77,2207.29 1007.77,2219.88 U1.4@1007.77,2275.75
NetC2_1: C2.1 FB1.1 R1.1 | length 130
  Top Layer w25: FB1.1@1246.67,2254.88 C2.1@1246.67,2319.88 R1.1@1246.67,2384.88
NetC4_1: C4.1 JP1.2 L1.2 U2.6 | length 400.4
  Top Layer w20: 580.18,2284.88 586.79,2291.5 U2.6@586.79,2324.29
  Top Layer w30: JP1.2@375.18,2149.88 375.18,2220.88 439.18,2284.88 L1.2@490.18,2284.88 530.18,2244.88 C4.1@578.68,2244.89 578.68,2283.39 580.18,2284.88
NetC5_1: C5.1 JP2.3 R2.1 U2.2 | length 466.8
  Top Layer w15: U2.2@663.56,2349.88 728.68,2349.88 R2.1@730.18,2348.39
  Top Layer w25: R2.1@730.18,2351.38 C5.1@805.18,2351.38 ; C5.1@806.67,2349.88 875.18,2349.88 896.67,2328.39 896.67,2259.88 950.18,2206.38 JP2.3@950.18,2124.88
NetC7_1: C7.1 FB2.1 R3.1 | length 147
  Top Layer w25: R3.1@685.18,1891.38 C7.1@760.18,1891.38 FB2.1@832.18,1891.38
NetC11_2: C11.2 R5.1 R6.2 R7.2 R47.1 | length 282
  Top Layer w10: R5.1@1466.5,1720 C11.2@1558.5,1720 R6.2@1558.5,1785 R7.2@1558.5,1910
NetC12_2: C12.2 R4.1 R5.2 | length 136.9
  Top Layer w7: C12.2@1335,1716.5 1338.5,1720 R5.2@1403.5,1720 ; R5.2@1402.87,1720.63 R4.1@1402.87,1787.6
NetC16_1: C16.1 C17.1 R14.2 R16.2 R31.1 U8.1 | length 727.8
  Top Layer w10: R31.1@572.5,872 609,872 625,856 624,855 624,842 623.5,841.5 C16.1@623.5,795 C17.1@623.5,665 R16.2@623.5,600 674.4,549.1 814.86,549.1 815.38,549.62 862.63,549.62 887.6,574.59 U8.1@887.6,690.87
NetC16_2: C16.2 R14.1 U7.4 | length 234
  Top Layer w10: R14.1@686.5,730 C16.2@686.5,795 691.5,800 710,800 735,825 805,825 810.59,819.41 U7.4@810.59,789.29
NetC17_2: C17.2 R16.1 U7.6 | length 233.1
  Top Layer w10: R16.1@686.5,600 C17.2@686.5,665 725,703.5 725,778.15 736.14,789.29 U7.6@759.41,789.29
NetC18_1: C18.1 R24.2 R33.1 U9.1 | length 218.7
  Top Layer w7: U9.1@1404.13,997.6 1404.13,974.84 1448.98,930 R24.2@1451.5,930 C18.1@1451.5,865 R33.1@1451.5,800
NetC18_2: C18.2 R23.2 R24.1 U9.4 | length 328.4
  Top Layer w7: U9.4@1295.87,1072.4 1322.6,1072.4 1330,1065 1330,988.5 R24.1@1388.5,930 C18.2@1388.5,865 R23.2@1321.5,865
NetC19_1: C19.1 J4.2 R20.1 U8.6 | length 474.7
  Top Layer w20: J4.2@655,1115 731.5,1038.5 R20.1@770,1038.5 770,892.01 793.5,868.5 C19.1@840,868.5 861.69,868.5 887.6,842.6 U8.6@887.6,799.13
NetC20_2: C20.2 R23.1 | length 91.1
  Top Layer w7: R23.1@1258.5,865 1321.5,927.99 C20.2@1321.5,930
NetC21_2: C21.2 R25.1 | length 70
  Top Layer w7: R25.1@960,931.5 C21.2@1030,931.5
NetC22_1: C22.1 J3.2 R19.1 U9.6 | length 390.9
  Top Layer w20: J3.2@915,1025 941.5,998.5 R19.1@1070,998.5 C22.1@1190,998.5 U9.6@1294.96,998.5
NetC23_2: C23.2 R39.2 U9.3 | length 136.9
  Top Layer w7: C23.2@1335,1143.5 1400,1143.5 R39.2@1403.5,1140 U9.3@1403.5,1073.03
NetC24_1: C24.1 R22.1 R31.2 | length 146.7
  Top Layer w10: R31.2@509.5,872 509.5,937 509.5,1018.01 R22.1@510,1018.5
NetC25_1: C25.1 R8.2 R21.2 R33.2 R34.2 | length 272
  Top Layer w7: R33.2@1388.5,800 C25.1@1321.5,800 R34.2@1321.5,735 1386.5,735 R8.2@1390,731.5 R21.2@1460,731.5
NetC27_2: C27.2 R36.1 R37.1 R40.2 | length 217.4
  Top Layer w10: 1096.5,670 1096.5,647.95 1055,606.46 1057.91,603.54 1125.45,603.54 C27.2@1125.45,538.54
NetC28_2: C28.2 R38.1 R39.1 R41.2 | length 222.6
  Top Layer w10: R39.1@1466.5,1140 1557.18,1140 1558.5,1138.68 1558.5,1073.68 R38.1@1558.5,1008.68
NetC29_1: C29.1 J7.2 R17.1 U10.3 | length 608.7
  Top Layer w10: U10.3@1037.2,312.6 1037.2,337.2 1050,350 1049.87,350.13 C29.1@1049.87,448.63
  Top Layer w20: J7.2@650,350 680,380 925,380 951.5,406.5 R17.1@951.5,450 C29.1@1048.5,450 C29.1@1049.87,448.63
NetC30_1: C30.1 R42.1 | length 67
  Top Layer w7: R42.1@1236.5,135 C30.1@1303.51,135
NetC31_1: C31.1 U10.2 | length 163.2
  Top Layer w10: U10.2@1062.79,312.6 1062.79,267.21 1080,250 C31.1@1173.5,250
NetC33_1: C33.1 R21.1 | length 426.5
  Top Layer w10: C33.1@1366.49,315 1425,315 1460,350 R21.1@1460,668.5
NetC33_2: C33.2 R45.1 | length 67
  Top Layer w7: R45.1@1236.49,315 C33.2@1303.5,315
